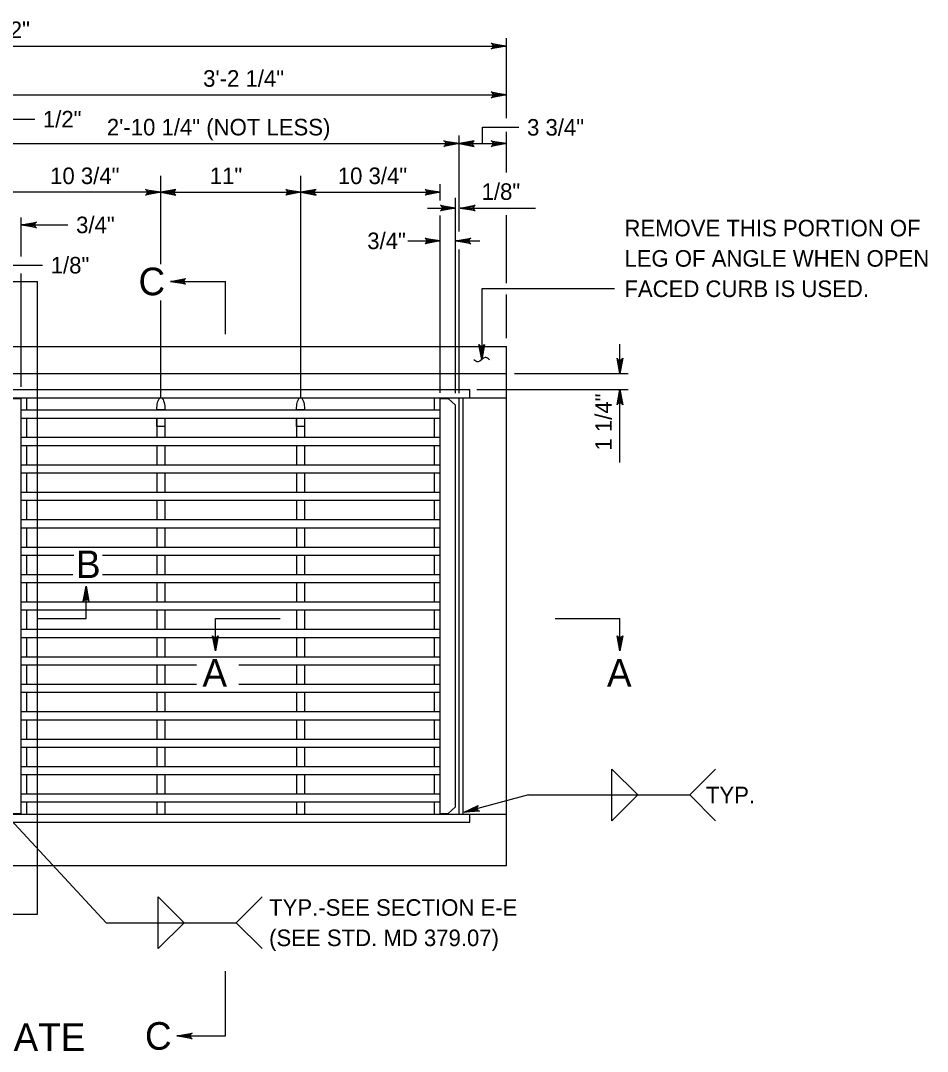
# Model space of a CAD drawing. Extents: x 0.7 to 7.67, y -7.49 to 2.47.
# Drawn here: x 3.951 to 7.24, y -1.264 to 2.473 of the extents above; entities that cross this region are included whole.
import ezdxf

# ---------------------------------------------------------------- set-up
doc = ezdxf.new("R2010")
doc.units = 0
for name, color, linetype in [('DETL-DIMS', 7, 'Continuous'), ('DETL-LINE', 7, 'Continuous'), ('DETL-NOTE', 7, 'Continuous'), ('DETL-TITL', 7, 'Continuous')]:
    doc.layers.add(name, color=color, linetype=linetype)

msp = doc.modelspace()

# ---------------------------------------------------------------- linework, layer by layer
at = {"layer": 'DETL-DIMS'}
for p, q in [((5.7132, 2.1198), (5.7132, 2.4099)), ((2.0269, 2.3805), (5.7132, 2.3805)), ((3.8707, 2.204), (5.7132, 2.204)), ((3.8848, 2.1158), (4.0025, 2.1158)), ((5.5416, 1.7086), (5.5416, 2.0569)), ((5.6263, 2.0262), (5.6263, 2.0862)), ((5.6263, 2.0862), (5.7587, 2.0862)), ((5.7132, 1.9225), (5.7132, 2.07)), ((3.8848, 2.0275), (5.7132, 2.0275)), ((4.4594, 1.5896), (4.4594, 1.9099)), ((4.9679, 1.106), (4.9679, 1.9099)), ((5.473, 1.8207), (5.473, 1.8805)), ((4.4594, 1.8511), (3.8946, 1.8511)), ((4.4594, 1.8511), (4.9679, 1.8511)), ((4.9679, 1.8511), (5.473, 1.8511)), ((5.5289, 1.1227), (5.5289, 1.8311)), ((3.9534, 1.6182), (3.9534, 1.7594)), ((5.4276, 1.7937), (5.5289, 1.7937)), ((5.473, 1.1238), (5.473, 1.7667)), ((5.5455, 1.7937), (5.8186, 1.7937)), ((5.7132, 1.5216), (5.7132, 1.7675)), ((3.9534, 1.7325), (4.1229, 1.7325)), ((5.3554, 1.6746), (5.473, 1.6746)), ((5.5289, 1.6746), (5.6165, 1.6746)), ((5.5416, 1.1227), (5.5416, 1.6432)), ((3.8939, 1.5864), (4.0308, 1.5864)), ((3.9534, 1.146), (3.9534, 1.5559)), ((4.4947, 1.5275), (4.6947, 1.5275)), ((4.6947, 1.3364), (4.6947, 1.5275)), ((5.6235, 1.501), (5.6235, 1.2442)), ((6.1048, 1.501), (5.6235, 1.501)), ((4.4594, 1.106), (4.4594, 1.4587)), ((5.7132, 1.3217), (5.7132, 1.4801)), ((6.125, 1.1942), (6.125, 1.3)), ((5.7426, 1.1942), (6.1544, 1.1942)), ((5.6057, 1.1354), (6.1544, 1.1354)), ((6.125, 0.8707), (6.125, 1.1354)), ((4.1887, 0.3053), (4.1887, 0.4225)), ((4.0122, 0.3053), (4.1887, 0.3053)), ((4.6577, 0.188), (4.6577, 0.3053)), ((4.6577, 0.3053), (4.8929, 0.3053)), ((5.8897, 0.3053), (6.125, 0.3053)), ((6.125, 0.188), (6.125, 0.3053)), ((5.7939, -0.3343), (5.5604, -0.3969)), ((5.7939, -0.3343), (5.9074, -0.3343)), ((4.262, -0.7972), (3.8847, -0.3909)), ((4.6947, -1.2078), (4.6947, -0.9725)), ((4.5182, -1.2078), (4.6947, -1.2078))]:
    msp.add_line(p, q, dxfattribs=at)
for points in [[(5.7132, 2.3805), (5.6584, 2.3702), (5.6626, 2.3731), (5.6648, 2.3768), (5.6654, 2.3805), (5.6648, 2.3842), (5.6626, 2.3878), (5.6584, 2.3908), (5.7132, 2.3805), (5.6626, 2.3878), (5.6648, 2.3842), (5.7132, 2.3805), (5.6654, 2.3805), (5.6648, 2.3768), (5.7132, 2.3805), (5.6626, 2.3731)], [(5.7132, 2.204), (5.6584, 2.1937), (5.6626, 2.1967), (5.6648, 2.2003), (5.6654, 2.204), (5.6648, 2.2077), (5.6626, 2.2114), (5.6584, 2.2143), (5.7132, 2.204), (5.6626, 2.2114), (5.6648, 2.2077), (5.7132, 2.204), (5.6654, 2.204), (5.6648, 2.2003), (5.7132, 2.204), (5.6626, 2.1967)], [(5.5416, 2.0275), (5.4868, 2.0173), (5.491, 2.0202), (5.4932, 2.0239), (5.4938, 2.0275), (5.4932, 2.0312), (5.491, 2.0349), (5.4868, 2.0378), (5.5416, 2.0275), (5.491, 2.0349), (5.4932, 2.0312), (5.5416, 2.0275), (5.4938, 2.0275), (5.4932, 2.0239), (5.5416, 2.0275), (5.491, 2.0202)], [(5.5416, 2.0275), (5.5965, 2.0173), (5.5922, 2.0202), (5.5901, 2.0239), (5.5894, 2.0275), (5.5901, 2.0312), (5.5922, 2.0349), (5.5965, 2.0378), (5.5416, 2.0275), (5.5922, 2.0349), (5.5901, 2.0312), (5.5416, 2.0275), (5.5894, 2.0275), (5.5901, 2.0239), (5.5416, 2.0275), (5.5922, 2.0202)], [(5.7132, 2.0275), (5.6584, 2.0173), (5.6626, 2.0202), (5.6648, 2.0239), (5.6654, 2.0275), (5.6648, 2.0312), (5.6626, 2.0349), (5.6584, 2.0378), (5.7132, 2.0275), (5.6626, 2.0349), (5.6648, 2.0312), (5.7132, 2.0275), (5.6654, 2.0275), (5.6648, 2.0239), (5.7132, 2.0275), (5.6626, 2.0202)], [(4.4594, 1.8511), (4.4045, 1.8408), (4.4088, 1.8437), (4.4109, 1.8474), (4.4116, 1.8511), (4.4109, 1.8547), (4.4088, 1.8584), (4.4045, 1.8613), (4.4594, 1.8511), (4.4088, 1.8584), (4.4109, 1.8547), (4.4594, 1.8511), (4.4116, 1.8511), (4.4109, 1.8474), (4.4594, 1.8511), (4.4088, 1.8437)], [(4.4594, 1.8511), (4.5142, 1.8408), (4.51, 1.8437), (4.5078, 1.8474), (4.5072, 1.8511), (4.5078, 1.8547), (4.51, 1.8584), (4.5142, 1.8613), (4.4594, 1.8511), (4.51, 1.8584), (4.5078, 1.8547), (4.4594, 1.8511), (4.5072, 1.8511), (4.5078, 1.8474), (4.4594, 1.8511), (4.51, 1.8437)], [(4.9679, 1.8511), (4.9131, 1.8408), (4.9173, 1.8437), (4.9195, 1.8474), (4.9202, 1.8511), (4.9195, 1.8547), (4.9173, 1.8584), (4.9131, 1.8613), (4.9679, 1.8511), (4.9173, 1.8584), (4.9195, 1.8547), (4.9679, 1.8511), (4.9202, 1.8511), (4.9195, 1.8474), (4.9679, 1.8511), (4.9173, 1.8437)], [(4.9679, 1.8511), (5.0228, 1.8408), (5.0185, 1.8437), (5.0164, 1.8474), (5.0157, 1.8511), (5.0164, 1.8547), (5.0185, 1.8584), (5.0228, 1.8613), (4.9679, 1.8511), (5.0185, 1.8584), (5.0164, 1.8547), (4.9679, 1.8511), (5.0157, 1.8511), (5.0164, 1.8474), (4.9679, 1.8511), (5.0185, 1.8437)], [(5.473, 1.8511), (5.4182, 1.8408), (5.4224, 1.8437), (5.4246, 1.8474), (5.4252, 1.8511), (5.4246, 1.8547), (5.4224, 1.8584), (5.4182, 1.8613), (5.473, 1.8511), (5.4224, 1.8584), (5.4246, 1.8547), (5.473, 1.8511), (5.4252, 1.8511), (5.4246, 1.8474), (5.473, 1.8511), (5.4224, 1.8437)], [(5.5289, 1.7937), (5.4741, 1.7834), (5.4783, 1.7864), (5.4805, 1.79), (5.4811, 1.7937), (5.4805, 1.7974), (5.4783, 1.8011), (5.4741, 1.804), (5.5289, 1.7937), (5.4783, 1.8011), (5.4805, 1.7974), (5.5289, 1.7937), (5.4811, 1.7937), (5.4805, 1.79), (5.5289, 1.7937), (5.4783, 1.7864)], [(5.5455, 1.7937), (5.6003, 1.804), (5.5961, 1.8011), (5.5939, 1.7974), (5.5933, 1.7937), (5.5939, 1.79), (5.5961, 1.7864), (5.6003, 1.7834), (5.5455, 1.7937), (5.5961, 1.7864), (5.5939, 1.79), (5.5455, 1.7937), (5.5933, 1.7937), (5.5939, 1.7974), (5.5455, 1.7937), (5.5961, 1.8011)], [(3.9534, 1.7325), (4.0082, 1.7428), (4.004, 1.7399), (4.0018, 1.7362), (4.0012, 1.7325), (4.0018, 1.7289), (4.004, 1.7252), (4.0082, 1.7223), (3.9534, 1.7325), (4.004, 1.7252), (4.0018, 1.7289), (3.9534, 1.7325), (4.0012, 1.7325), (4.0018, 1.7362), (3.9534, 1.7325), (4.004, 1.7399)], [(5.473, 1.6746), (5.4182, 1.6643), (5.4224, 1.6672), (5.4246, 1.6709), (5.4252, 1.6746), (5.4246, 1.6783), (5.4224, 1.6819), (5.4182, 1.6849), (5.473, 1.6746), (5.4224, 1.6819), (5.4246, 1.6783), (5.473, 1.6746), (5.4252, 1.6746), (5.4246, 1.6709), (5.473, 1.6746), (5.4224, 1.6672)], [(5.5289, 1.6746), (5.5837, 1.6849), (5.5795, 1.6819), (5.5773, 1.6783), (5.5767, 1.6746), (5.5773, 1.6709), (5.5795, 1.6672), (5.5837, 1.6643), (5.5289, 1.6746), (5.5795, 1.6672), (5.5773, 1.6709), (5.5289, 1.6746), (5.5767, 1.6746), (5.5773, 1.6783), (5.5289, 1.6746), (5.5795, 1.6819)], [(4.4947, 1.5275), (4.5496, 1.5378), (4.5453, 1.5349), (4.5432, 1.5312), (4.5425, 1.5275), (4.5432, 1.5239), (4.5453, 1.5202), (4.5496, 1.5173), (4.4947, 1.5275), (4.5453, 1.5202), (4.5432, 1.5239), (4.4947, 1.5275), (4.5425, 1.5275), (4.5432, 1.5312), (4.4947, 1.5275), (4.5453, 1.5349)], [(5.6235, 1.2442), (5.6133, 1.299), (5.6162, 1.2948), (5.6199, 1.2926), (5.6235, 1.2919), (5.6272, 1.2926), (5.6309, 1.2948), (5.6338, 1.299), (5.6235, 1.2442), (5.6309, 1.2948), (5.6272, 1.2926), (5.6235, 1.2442), (5.6235, 1.2919), (5.6199, 1.2926), (5.6235, 1.2442), (5.6162, 1.2948)], [(6.125, 1.1942), (6.1147, 1.249), (6.1176, 1.2448), (6.1213, 1.2426), (6.125, 1.242), (6.1286, 1.2426), (6.1323, 1.2448), (6.1353, 1.249), (6.125, 1.1942), (6.1323, 1.2448), (6.1286, 1.2426), (6.125, 1.1942), (6.125, 1.242), (6.1213, 1.2426), (6.125, 1.1942), (6.1176, 1.2448)], [(6.125, 1.1354), (6.1353, 1.0806), (6.1323, 1.0848), (6.1286, 1.087), (6.125, 1.0876), (6.1213, 1.087), (6.1176, 1.0848), (6.1147, 1.0806), (6.125, 1.1354), (6.1176, 1.0848), (6.1213, 1.087), (6.125, 1.1354), (6.125, 1.0876), (6.1286, 1.087), (6.125, 1.1354), (6.1323, 1.0848)], [(4.1887, 0.4225), (4.199, 0.3677), (4.196, 0.3719), (4.1924, 0.3741), (4.1887, 0.3747), (4.185, 0.3741), (4.1813, 0.3719), (4.1784, 0.3677), (4.1887, 0.4225), (4.1813, 0.3719), (4.185, 0.3741), (4.1887, 0.4225), (4.1887, 0.3747), (4.1924, 0.3741), (4.1887, 0.4225), (4.196, 0.3719)], [(4.6577, 0.188), (4.6474, 0.2428), (4.6503, 0.2386), (4.654, 0.2364), (4.6577, 0.2358), (4.6613, 0.2364), (4.665, 0.2386), (4.6679, 0.2428), (4.6577, 0.188), (4.665, 0.2386), (4.6613, 0.2364), (4.6577, 0.188), (4.6577, 0.2358), (4.654, 0.2364), (4.6577, 0.188), (4.6503, 0.2386)], [(6.125, 0.188), (6.1147, 0.2428), (6.1176, 0.2386), (6.1213, 0.2364), (6.125, 0.2358), (6.1286, 0.2364), (6.1323, 0.2386), (6.1353, 0.2428), (6.125, 0.188), (6.1323, 0.2386), (6.1286, 0.2364), (6.125, 0.188), (6.125, 0.2358), (6.1213, 0.2364), (6.125, 0.188), (6.1176, 0.2386)], [(5.9074, -0.3343), (6.1898, -0.3343), (6.0957, -0.4284), (6.0957, -0.2401), (6.1898, -0.3343), (6.378, -0.3343)], [(6.4721, -0.2401), (6.378, -0.3343), (6.4721, -0.4284)], [(5.5604, -0.3969), (5.6107, -0.3728), (5.6074, -0.3767), (5.6063, -0.3808), (5.6066, -0.3845), (5.6082, -0.3879), (5.6112, -0.3909), (5.6161, -0.3926), (5.5604, -0.3969), (5.6112, -0.3909), (5.6082, -0.3879), (5.5604, -0.3969), (5.6066, -0.3845), (5.6063, -0.3808), (5.5604, -0.3969), (5.6074, -0.3767)], [(4.262, -0.7972), (4.5443, -0.7972), (4.4502, -0.8913), (4.4502, -0.7031), (4.5443, -0.7972), (4.7326, -0.7972)], [(4.8267, -0.7031), (4.7326, -0.7972), (4.8267, -0.8913)], [(4.5182, -1.2078), (4.573, -1.1975), (4.5688, -1.2004), (4.5666, -1.2041), (4.566, -1.2078), (4.5666, -1.2114), (4.5688, -1.2151), (4.573, -1.218), (4.5182, -1.2078), (4.5688, -1.2151), (4.5666, -1.2114), (4.5182, -1.2078), (4.566, -1.2078), (4.5666, -1.2041), (4.5182, -1.2078), (4.5688, -1.2004)]]:
    msp.add_lwpolyline(points, dxfattribs=at)
msp.add_spline([(5.6522, 1.2436), (5.6363, 1.2521), (5.6106, 1.2362), (5.595, 1.2438)], degree=3, dxfattribs=at)
at = {"layer": 'DETL-LINE'}
for p, q in [((3.7279, 1.5275), (4.0122, 1.5275)), ((4.0122, -0.7666), (4.0122, 1.5275)), ((2.6886, 1.2922), (5.7132, 1.2922)), ((5.7132, -0.5901), (5.7132, 1.2922)), ((2.0269, 1.1942), (5.7132, 1.1942)), ((2.1593, 1.1354), (5.5809, 1.1354)), ((5.5809, 1.106), (5.5809, 1.1354)), ((2.0269, 1.106), (5.7132, 1.106)), ((3.924, 1.1034), (3.9534, 1.1034)), ((3.9534, -0.4038), (3.9534, 1.106)), ((3.974, 1.0619), (3.974, 1.106)), ((5.4524, 1.0619), (5.4524, 1.106)), ((5.473, -0.4038), (5.473, 1.106)), ((5.473, 1.1033), (5.5024, 1.1033)), ((5.5289, 1.0792), (5.5024, 1.1033)), ((5.5416, -0.4038), (5.5416, 1.106)), ((5.5563, -0.4038), (5.5563, 1.106)), ((3.9534, 1.0619), (5.473, 1.0619)), ((5.5289, -0.3771), (5.5289, 1.0792)), ((3.9534, 1.0324), (5.473, 1.0324)), ((3.974, 0.9624), (3.974, 1.0324)), ((4.4452, 1.0324), (4.4452, 0.9624)), ((4.4746, 1.0324), (4.4746, 0.9624)), ((4.9518, 1.0324), (4.9518, 0.9624)), ((4.9812, 1.0324), (4.9812, 0.9624)), ((5.4524, 0.9624), (5.4524, 1.0324)), ((3.9534, 0.9624), (5.473, 0.9624)), ((3.9534, 0.933), (5.473, 0.933)), ((3.974, 0.863), (3.974, 0.933)), ((4.4452, 0.933), (4.4452, 0.863)), ((4.4746, 0.933), (4.4746, 0.863)), ((4.9518, 0.933), (4.9518, 0.863)), ((4.9812, 0.933), (4.9812, 0.863)), ((5.4524, 0.863), (5.4524, 0.933)), ((3.9534, 0.863), (5.473, 0.863)), ((3.9534, 0.8336), (5.473, 0.8336)), ((3.974, 0.7635), (3.974, 0.8336)), ((4.4452, 0.8336), (4.4452, 0.7635)), ((4.4746, 0.8336), (4.4746, 0.7635)), ((4.9518, 0.8336), (4.9518, 0.7635)), ((4.9812, 0.8336), (4.9812, 0.7635)), ((5.4524, 0.7635), (5.4524, 0.8336)), ((3.9534, 0.7635), (5.473, 0.7635)), ((3.9534, 0.7341), (5.473, 0.7341)), ((3.974, 0.6641), (3.974, 0.7341)), ((4.4452, 0.7341), (4.4452, 0.6641)), ((4.4746, 0.7341), (4.4746, 0.6641)), ((4.9518, 0.7341), (4.9518, 0.6641)), ((4.9812, 0.7341), (4.9812, 0.6641)), ((5.4524, 0.6641), (5.4524, 0.7341)), ((3.9534, 0.6641), (5.473, 0.6641)), ((3.9534, 0.6347), (5.473, 0.6347)), ((3.974, 0.5646), (3.974, 0.6347)), ((4.4452, 0.6347), (4.4452, 0.5646)), ((4.4746, 0.6347), (4.4746, 0.5646)), ((4.9518, 0.6347), (4.9518, 0.5646)), ((4.9812, 0.6347), (4.9812, 0.5646)), ((5.4524, 0.5646), (5.4524, 0.6347)), ((3.9534, 0.5646), (5.473, 0.5646)), ((3.9534, 0.5352), (4.1441, 0.5352)), ((3.974, 0.4652), (3.974, 0.5352)), ((4.2487, 0.5352), (5.473, 0.5352)), ((4.4452, 0.5352), (4.4452, 0.4652)), ((4.4746, 0.5352), (4.4746, 0.4652)), ((4.9518, 0.5352), (4.9518, 0.4652)), ((4.9812, 0.5352), (4.9812, 0.4652)), ((5.4524, 0.4652), (5.4524, 0.5352)), ((3.9534, 0.4652), (4.1409, 0.4652)), ((4.2487, 0.4652), (5.473, 0.4652)), ((3.9534, 0.4358), (5.473, 0.4358)), ((3.974, 0.3658), (3.974, 0.4358)), ((4.4452, 0.4358), (4.4452, 0.3658)), ((4.4746, 0.4358), (4.4746, 0.3658)), ((4.9518, 0.4358), (4.9518, 0.3658)), ((4.9812, 0.4358), (4.9812, 0.3658)), ((5.4524, 0.3658), (5.4524, 0.4358)), ((3.9534, 0.3658), (5.473, 0.3658)), ((3.9534, 0.3364), (5.473, 0.3364)), ((3.974, 0.2663), (3.974, 0.3364)), ((4.4452, 0.3364), (4.4452, 0.2663)), ((4.4746, 0.3364), (4.4746, 0.2663)), ((4.9518, 0.3364), (4.9518, 0.2663)), ((4.9812, 0.3364), (4.9812, 0.2663)), ((5.4524, 0.2663), (5.4524, 0.3364)), ((3.9534, 0.2663), (5.473, 0.2663)), ((3.9534, 0.2369), (5.473, 0.2369)), ((3.974, 0.1669), (3.974, 0.2369)), ((4.4452, 0.2369), (4.4452, 0.1669)), ((4.4746, 0.2369), (4.4746, 0.1669)), ((4.9518, 0.2369), (4.9518, 0.1669)), ((4.9812, 0.2369), (4.9812, 0.1669)), ((5.4524, 0.1669), (5.4524, 0.2369)), ((3.9534, 0.1669), (5.473, 0.1669)), ((3.9534, 0.1375), (4.5885, 0.1375)), ((3.974, 0.0674), (3.974, 0.1375)), ((4.4452, 0.1375), (4.4452, 0.0674)), ((4.4746, 0.1375), (4.4746, 0.0674)), ((4.7421, 0.1375), (5.473, 0.1375)), ((4.9518, 0.1375), (4.9518, 0.0674)), ((4.9812, 0.1375), (4.9812, 0.0674)), ((5.4524, 0.0674), (5.4524, 0.1375)), ((3.9534, 0.0674), (4.5885, 0.0674)), ((3.9534, 0.038), (5.473, 0.038)), ((3.974, -0.032), (3.974, 0.038)), ((4.4452, 0.038), (4.4452, -0.032)), ((4.4746, 0.038), (4.4746, -0.032)), ((4.7421, 0.0674), (5.473, 0.0674)), ((4.9518, 0.038), (4.9518, -0.032)), ((4.9812, 0.038), (4.9812, -0.032)), ((5.4524, -0.032), (5.4524, 0.038)), ((3.9534, -0.032), (5.473, -0.032)), ((3.9534, -0.0614), (5.473, -0.0614)), ((3.974, -0.1314), (3.974, -0.0614)), ((4.4452, -0.0614), (4.4452, -0.1314)), ((4.4746, -0.0614), (4.4746, -0.1314)), ((4.9518, -0.0614), (4.9518, -0.1314)), ((4.9812, -0.0614), (4.9812, -0.1314)), ((5.4524, -0.1314), (5.4524, -0.0614)), ((3.9534, -0.1314), (5.473, -0.1314)), ((3.9534, -0.1609), (5.473, -0.1609)), ((3.974, -0.2309), (3.974, -0.1609)), ((4.4452, -0.1609), (4.4452, -0.2309)), ((4.4746, -0.1609), (4.4746, -0.2309)), ((4.9518, -0.1609), (4.9518, -0.2309)), ((4.9812, -0.1609), (4.9812, -0.2309)), ((5.4524, -0.2309), (5.4524, -0.1609)), ((3.9534, -0.2309), (5.473, -0.2309)), ((3.9534, -0.2603), (5.473, -0.2603)), ((3.974, -0.3303), (3.974, -0.2603)), ((4.4452, -0.2603), (4.4452, -0.3303)), ((4.4746, -0.2603), (4.4746, -0.3303)), ((4.9518, -0.2603), (4.9518, -0.3303)), ((4.9812, -0.2603), (4.9812, -0.3303)), ((5.4524, -0.3303), (5.4524, -0.2603)), ((3.9534, -0.3303), (5.473, -0.3303)), ((3.9534, -0.3597), (5.473, -0.3597)), ((3.974, -0.4038), (3.974, -0.3597)), ((4.4452, -0.3597), (4.4452, -0.4038)), ((4.4746, -0.3597), (4.4746, -0.4038)), ((4.9518, -0.3597), (4.9518, -0.4038)), ((4.9812, -0.3597), (4.9812, -0.4038)), ((5.4524, -0.4038), (5.4524, -0.3597)), ((2.0269, -0.4038), (5.7132, -0.4038)), ((3.924, -0.401), (3.9534, -0.401)), ((5.473, -0.4012), (5.5024, -0.4012)), ((5.5289, -0.3771), (5.5024, -0.4012)), ((5.5809, -0.4332), (5.5809, -0.4038)), ((2.1593, -0.4332), (5.5809, -0.4332)), ((2.0269, -0.5901), (5.7132, -0.5901)), ((3.7279, -0.7666), (4.0122, -0.7666))]:
    msp.add_line(p, q, dxfattribs=at)
for points in [[(4.4452, 1.0619), (4.4455, 1.0705), (4.446, 1.0752), (4.4464, 1.0788), (4.4468, 1.0827), (4.4478, 1.0874), (4.4491, 1.0925), (4.4511, 1.0972), (4.4535, 1.1018), (4.4556, 1.1042), (4.4578, 1.1058), (4.46, 1.106), (4.4617, 1.106), (4.463, 1.1052), (4.4646, 1.1038), (4.4659, 1.1022), (4.4676, 1.0995), (4.4699, 1.0945), (4.4718, 1.0883), (4.4729, 1.0825), (4.4737, 1.0774), (4.4742, 1.0729), (4.4745, 1.0686), (4.4746, 1.0619)], [(4.9518, 1.0619), (4.9521, 1.0705), (4.9525, 1.0752), (4.9529, 1.0788), (4.9534, 1.0827), (4.9544, 1.0874), (4.9557, 1.0925), (4.9576, 1.0972), (4.96, 1.1018), (4.9621, 1.1042), (4.9643, 1.1058), (4.9665, 1.106), (4.9682, 1.106), (4.9695, 1.1052), (4.9711, 1.1038), (4.9724, 1.1022), (4.9741, 1.0995), (4.9764, 1.0945), (4.9783, 1.0883), (4.9794, 1.0825), (4.9802, 1.0774), (4.9807, 1.0729), (4.9811, 1.0686), (4.9812, 1.0619)], [(4.4452, 1.0324), (4.4743, 1.0324), (4.4743, 1.0014), (4.4452, 1.0014)], [(4.9518, 1.0324), (4.9808, 1.0324), (4.9808, 1.0014), (4.9518, 1.0014)]]:
    msp.add_lwpolyline(points, close=True, dxfattribs=at)

# ---------------------------------------------------------------- texts
at = {"layer": 'DETL-NOTE'}
for s, p in [('6\'-4 1/2"', (3.6913, 2.4099)), ('3\'-2 1/4"', (4.6132, 2.2334)), ('1/2"', (4.0319, 2.0858)), ('2\'-10 1/4" (NOT LESS)', (4.264, 2.0569)), ('3 3/4"', (5.7881, 2.0562)), ('10 3/4"', (4.0582, 1.8805)), ('10 3/4"', (5.1017, 1.8805)), ('11"', (4.6373, 1.8805)), ('1/8"', (5.6233, 1.8231)), ('3/4"', (4.1523, 1.7025)), ('REMOVE THIS PORTION OF ', (6.1412, 1.691)), ('3/4"', (5.2085, 1.6446)), ('1/8"', (4.0603, 1.5564)), ('LEG OF ANGLE WHEN OPEN', (6.1412, 1.581)), ('FACED CURB IS USED.', (6.1412, 1.471)), ('TYP.', (6.4369, -0.3643)), ('TYP.-SEE SECTION E-E', (4.8524, -0.7722)), ('(SEE STD. MD 379.07)', (4.8524, -0.8822))]:
    msp.add_text(s, height=0.06, dxfattribs=at).set_placement(p)
msp.add_text('1 1/4"', height=0.06, rotation=90, dxfattribs=at).set_placement((6.0956, 0.9143))
at = {"layer": 'DETL-TITL'}
for s, p in [('C', (4.3788, 1.4775)), ('B', (4.152, 0.452)), ('A', (4.6107, 0.0586)), ('A', (6.078, 0.0586)), ('C', (4.4022, -1.2578)), ('DOUBLE GRATE', (3.1381, -1.2624))]:
    msp.add_text(s, height=0.1, dxfattribs=at).set_placement(p)

doc.saveas('drawing.dxf')
